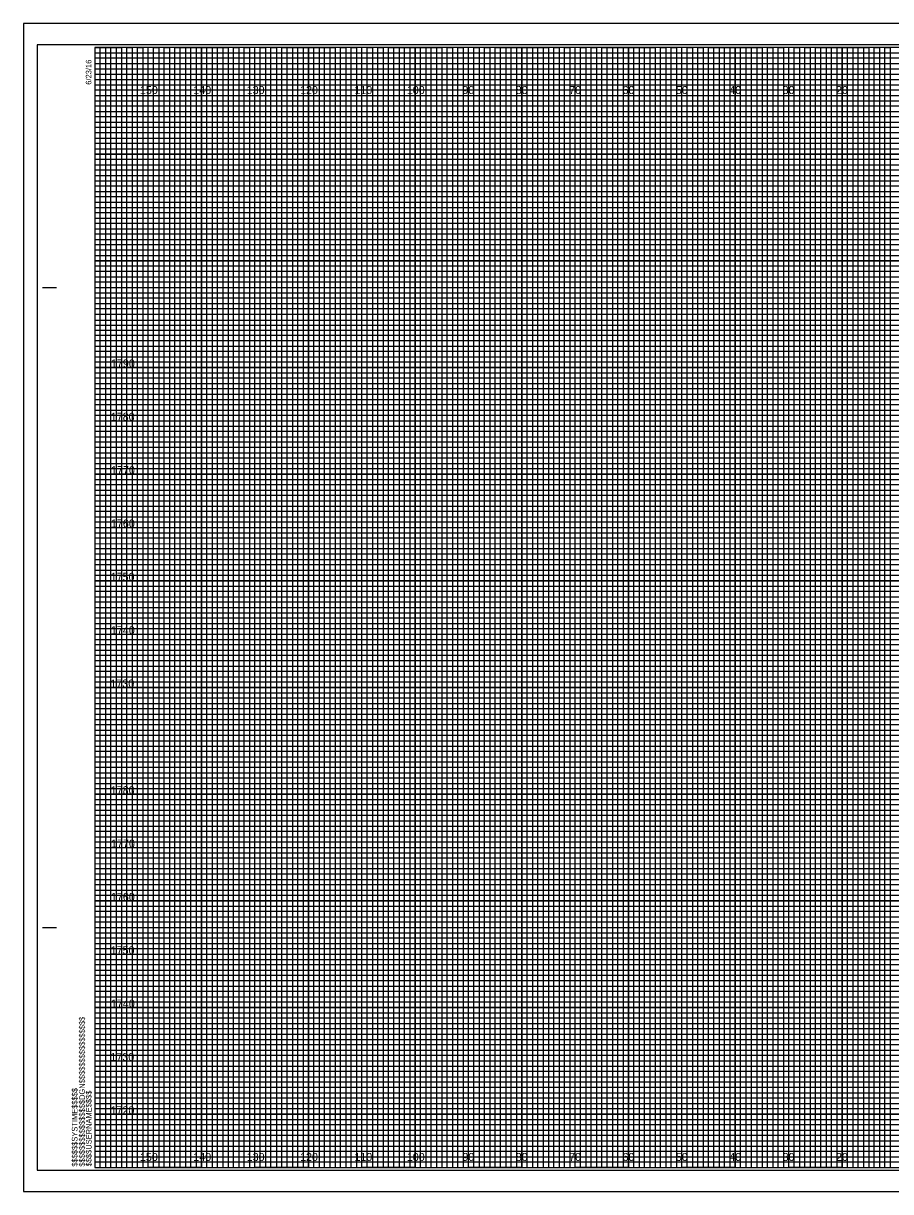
# Model space of a CAD drawing. Extents: x 570 to 907, y -9 to 870.
# Drawn here: x 570.4 to 732.9, y 430.6 to 649.6 of the extents above; entities that cross this region are included whole.
import ezdxf

# ---------------------------------------------------------------- set-up
doc = ezdxf.new("R2010")
doc.units = 0
for name, color, linetype in [('Prop XS Earthwork Shape', 7, 'Continuous'), ('Raster_Level_0', 7, 'Continuous'), ('Scratch_Level_3', 7, 'Continuous'), ('Sheet Cross Section CELL', 7, 'Continuous'), ('Sheet Cross Section Grid Middle CELL', 7, 'Continuous'), ('Sheet Cross Section Grid Minor 1 CELL', 7, 'Continuous'), ('Sheet Cross Section Grid Minor 2 CELL', 7, 'Continuous'), ('Sheet Cutting Line CELL', 7, 'Continuous'), ('Sheet DOT Grid CELL', 7, 'Continuous'), ('Sheet Plot Border Inside CELL', 7, 'Continuous'), ('Sheet Plot Border Outside CELL', 7, 'Continuous')]:
    doc.layers.add(name, color=color, linetype=linetype)

msp = doc.modelspace()

# ---------------------------------------------------------------- linework, layer by layer
at = {"layer": 'Prop XS Earthwork Shape'}
for p, q in [((593.77, 645.14), (583.77, 645.14)), ((593.77, 435.14), (593.77, 645.14)), ((613.77, 645.14), (603.77, 645.14)), ((603.77, 645.14), (603.77, 435.14)), ((613.77, 435.14), (613.77, 645.14)), ((633.77, 645.14), (623.77, 645.14)), ((623.77, 645.14), (623.77, 435.14)), ((633.77, 435.14), (633.77, 645.14)), ((653.77, 645.14), (643.77, 645.14)), ((643.77, 645.14), (643.77, 435.14)), ((653.77, 435.14), (653.77, 645.14)), ((673.77, 645.14), (663.77, 645.14)), ((663.77, 645.14), (663.77, 435.14)), ((673.77, 435.14), (673.77, 645.14)), ((693.77, 645.14), (683.77, 645.14)), ((683.77, 645.14), (683.77, 435.14)), ((693.77, 435.14), (693.77, 645.14)), ((713.77, 645.14), (703.77, 645.14)), ((703.77, 645.14), (703.77, 435.14)), ((713.77, 435.14), (713.77, 645.14)), ((733.77, 645.14), (723.77, 645.14)), ((723.77, 645.14), (723.77, 435.14)), ((603.77, 435.14), (593.77, 435.14)), ((623.77, 435.14), (613.77, 435.14)), ((643.77, 435.14), (633.77, 435.14)), ((663.77, 435.14), (653.77, 435.14)), ((683.77, 435.14), (673.77, 435.14)), ((703.77, 435.14), (693.77, 435.14)), ((723.77, 435.14), (713.77, 435.14))]:
    msp.add_line(p, q, dxfattribs=at)
for points in [[(583.77, 635.14), (903.77, 635.14), (903.77, 625.14), (583.77, 625.14)], [(583.77, 615.14), (903.77, 615.14), (903.77, 605.14), (583.77, 605.14)], [(583.77, 595.14), (903.77, 595.14), (903.77, 585.14), (583.77, 585.14)], [(583.77, 575.14), (903.77, 575.14), (903.77, 565.14), (583.77, 565.14)], [(583.77, 555.14), (903.77, 555.14), (903.77, 545.14), (583.77, 545.14)], [(583.77, 535.14), (903.77, 535.14), (903.77, 525.14), (583.77, 525.14)], [(583.77, 515.14), (903.77, 515.14), (903.77, 505.14), (583.77, 505.14)], [(583.77, 495.14), (903.77, 495.14), (903.77, 485.14), (583.77, 485.14)], [(583.77, 475.14), (903.77, 475.14), (903.77, 465.14), (583.77, 465.14)], [(583.77, 455.14), (903.77, 455.14), (903.77, 445.14), (583.77, 445.14)]]:
    msp.add_lwpolyline(points, dxfattribs=at)
at = {"layer": 'Sheet Cross Section CELL'}
for p, q in [((573.97, 600.14), (576.47, 600.14)), ((574.07, 600.14), (576.57, 600.14)), ((573.97, 480.14), (576.47, 480.14)), ((574.07, 480.14), (576.57, 480.14)), ((583.77, 435.14), (583.77, 435.14)), ((583.77, 435.14), (583.77, 435.14)), ((583.77, 435.14), (583.77, 435.14)), ((583.77, 435.14), (583.77, 435.14)), ((583.77, 435.14), (583.77, 435.14)), ((583.77, 435.14), (583.77, 435.14)), ((583.77, 435.14), (583.77, 435.14))]:
    msp.add_line(p, q, dxfattribs=at)
msp.add_lwpolyline([(903.77, 645.14), (583.77, 645.14), (583.77, 435.14), (903.77, 435.14)], close=True, dxfattribs=at)
at = {"layer": 'Sheet Cross Section Grid Middle CELL'}
for points in [[(583.77, 645.14), (588.77, 645.14), (588.77, 435.14), (598.77, 435.14), (598.77, 645.14), (608.77, 645.14), (608.77, 435.14), (618.77, 435.14), (618.77, 645.14), (628.77, 645.14), (628.77, 435.14), (638.77, 435.14), (638.77, 645.14), (648.77, 645.14), (648.77, 435.14), (658.77, 435.14), (658.77, 645.14), (668.77, 645.14), (668.77, 435.14), (678.77, 435.14), (678.77, 645.14), (688.77, 645.14), (688.77, 435.14), (698.77, 435.14), (698.77, 645.14), (708.77, 645.14), (708.77, 435.14), (718.77, 435.14), (718.77, 645.14), (728.77, 645.14), (728.77, 435.14), (738.77, 435.14)], [(583.77, 640.14), (858.77, 640.14)], [(583.77, 620.14), (903.77, 620.14), (903.77, 630.14), (583.77, 630.14)], [(583.77, 600.14), (903.77, 600.14), (903.77, 610.14), (583.77, 610.14)], [(583.77, 580.14), (903.77, 580.14), (903.77, 590.14), (583.77, 590.14)], [(583.77, 560.14), (903.77, 560.14), (903.77, 570.14), (583.77, 570.14)], [(583.77, 540.14), (903.77, 540.14), (903.77, 550.14), (583.77, 550.14)], [(583.77, 520.14), (903.77, 520.14), (903.77, 530.14), (583.77, 530.14)], [(583.77, 500.14), (903.77, 500.14), (903.77, 510.14), (583.77, 510.14)], [(583.77, 480.14), (903.77, 480.14), (903.77, 490.14), (583.77, 490.14)], [(583.77, 460.14), (903.77, 460.14), (903.77, 470.14), (583.77, 470.14)], [(583.77, 440.14), (903.77, 440.14), (903.77, 450.14), (583.77, 450.14)]]:
    msp.add_lwpolyline(points, dxfattribs=at)
at = {"layer": 'Sheet Cross Section Grid Minor 1 CELL'}
for p, q in [((583.77, 644.14), (843.77, 644.14)), ((843.77, 643.12), (583.77, 643.12)), ((583.77, 643.12), (583.77, 642.14)), ((583.77, 642.14), (843.77, 642.14)), ((843.77, 641.03), (583.77, 641.03)), ((583.77, 641.03), (583.77, 639.14)), ((583.77, 639.14), (903.77, 639.14))]:
    msp.add_line(p, q, dxfattribs=at)
for points in [[(583.77, 638.14), (853.77, 638.14), (903.77, 638.14), (903.77, 637.14), (583.77, 637.14)], [(583.77, 636.14), (903.77, 636.14), (903.77, 634.14), (583.77, 634.14)], [(583.77, 633.14), (903.77, 633.14), (903.77, 632.14), (583.77, 632.12)], [(583.77, 631.14), (903.77, 631.14), (903.77, 629.14), (583.77, 629.14)], [(583.77, 628.14), (903.77, 628.14), (903.77, 627.14), (583.77, 627.14)], [(583.77, 626.14), (903.77, 626.14), (903.77, 624.14), (583.77, 624.14)], [(583.77, 623.14), (903.77, 623.14), (903.77, 622.14), (583.77, 622.14)], [(583.77, 621.14), (903.77, 621.14), (903.77, 619.14), (583.77, 619.14)], [(583.77, 618.14), (903.77, 618.14), (903.77, 617.14), (583.77, 617.14)], [(583.77, 616.14), (903.77, 616.14), (903.77, 614.14), (583.77, 614.14)], [(583.77, 613.14), (903.77, 613.14), (903.77, 612.14), (583.77, 612.14)], [(583.77, 611.14), (903.77, 611.14), (903.77, 609.09), (903.77, 608.14), (903.77, 607.14), (583.77, 607.14)], [(583.77, 609.14), (903.77, 609.14), (903.77, 608.14), (583.77, 608.14)], [(583.77, 606.14), (903.77, 606.14), (903.77, 604.14), (583.77, 604.17)], [(583.77, 604.17), (903.77, 604.14), (903.77, 603.14), (583.77, 603.14)], [(583.77, 602.14), (903.77, 602.14), (903.77, 601.14), (583.77, 601.14)], [(583.77, 599.14), (903.77, 599.14), (903.77, 598.14), (583.77, 598.14)], [(583.77, 597.14), (903.77, 597.14), (903.77, 596.14), (583.77, 596.14)], [(583.7, 594.03), (903.77, 594.03), (903.77, 593.02), (583.7, 593.02)], [(583.77, 592.14), (903.77, 592.14), (903.77, 591.14), (583.77, 591.14)], [(583.77, 589.14), (903.77, 589.14), (903.77, 588.14), (583.77, 588.14)], [(583.77, 587.14), (903.77, 587.14), (903.77, 586.14), (583.77, 586.14)], [(583.77, 584.14), (903.77, 584.14), (903.77, 583.14), (583.77, 583.14)], [(583.77, 582.14), (903.77, 582.14), (903.77, 581.14), (583.77, 581.14)], [(583.77, 579.14), (903.77, 579.14), (903.77, 578.14), (583.77, 578.14)], [(583.77, 577.14), (903.77, 577.14), (903.77, 576.14), (583.77, 576.14)], [(583.77, 574.14), (903.77, 574.14), (903.76, 573.12), (583.77, 573.14)], [(583.77, 572.14), (903.77, 572.14), (903.77, 571.14), (583.77, 571.14)], [(583.77, 569.14), (903.77, 569.14), (903.77, 568.14), (583.77, 568.14)], [(583.77, 567.14), (903.77, 567.14), (903.77, 566.14), (583.77, 566.14)], [(583.77, 564.14), (903.77, 564.14), (903.77, 563.14), (583.77, 563.14)], [(583.77, 562.14), (903.77, 562.14), (903.77, 561.14), (583.77, 561.14)], [(583.77, 559.14), (903.77, 559.14), (903.77, 558.14), (583.77, 558.14)], [(583.77, 557.14), (903.77, 557.14), (903.77, 556.14), (583.77, 556.14)], [(583.77, 554.14), (903.77, 554.14), (903.77, 553.14), (583.77, 553.14)], [(583.77, 552.13), (903.84, 552.05), (903.77, 551.14), (583.77, 551.14)], [(583.77, 549.14), (903.77, 549.14), (903.77, 548.14), (583.77, 548.14)], [(583.77, 547.14), (903.77, 547.14), (903.77, 546.14), (583.77, 546.14)], [(583.77, 544.14), (903.77, 544.14), (903.77, 543.14), (583.77, 543.14)], [(583.77, 542.14), (903.77, 542.14), (903.77, 541.14), (583.77, 541.14)], [(583.77, 539.14), (903.77, 539.14), (903.77, 538.14), (583.77, 538.14)], [(583.77, 537.14), (903.77, 537.14), (903.77, 536.14), (583.77, 536.14)], [(583.77, 534.14), (903.77, 534.14), (903.77, 533.14), (583.77, 533.14)], [(583.77, 532.14), (903.77, 532.14), (903.77, 531.14), (583.77, 531.14)], [(583.77, 529.14), (903.77, 529.14), (903.77, 528.14), (583.77, 528.14)], [(583.77, 527.14), (903.77, 527.14), (903.77, 526.14), (583.77, 526.14)], [(583.77, 524.14), (903.77, 524.14), (903.77, 523.14), (583.77, 523.14)], [(583.77, 522.14), (903.77, 522.14), (903.77, 521.14), (583.77, 521.14)], [(583.77, 519.14), (903.77, 519.14), (903.77, 518.14), (583.77, 518.14)], [(583.77, 517.14), (903.77, 517.14), (903.77, 516.14), (583.77, 516.14)], [(583.77, 514.14), (903.77, 514.14), (903.76, 513.12), (583.77, 513.14)], [(583.77, 512.14), (903.77, 512.14), (903.77, 511.14), (583.77, 511.14)], [(583.77, 509.14), (903.77, 509.14), (903.77, 508.14), (583.77, 508.14)], [(583.77, 507.14), (903.77, 507.14), (903.77, 506.14), (583.77, 506.14)], [(583.77, 504.14), (903.77, 504.14), (903.77, 503.14), (583.77, 503.14)], [(583.77, 502.14), (903.77, 502.14), (903.77, 501.14), (583.77, 501.14)], [(583.77, 499.14), (903.77, 499.14), (903.77, 498.14), (583.77, 498.14)], [(583.77, 497.14), (903.77, 497.14), (903.77, 496.14), (583.77, 496.14)], [(583.77, 494.14), (903.77, 494.14), (903.77, 493.14), (583.77, 493.14)], [(583.77, 492.13), (903.84, 492.05), (903.77, 491.14), (583.77, 491.14)], [(583.77, 489.14), (903.77, 489.14), (903.77, 488.14), (583.77, 488.14)], [(583.77, 487.14), (903.77, 487.14), (903.77, 486.14), (583.77, 486.14)], [(583.77, 484.14), (903.77, 484.14), (903.77, 483.14), (583.77, 483.14)], [(583.77, 482.14), (903.77, 482.14), (903.77, 481.14), (583.77, 481.14)], [(583.77, 479.14), (903.77, 479.14), (903.77, 478.14), (583.77, 478.14)], [(583.77, 477.14), (903.77, 477.14), (903.77, 476.14), (583.77, 476.14)], [(583.77, 474.14), (903.77, 474.14), (903.77, 473.14), (583.77, 473.14)], [(583.77, 472.14), (903.77, 472.14), (903.77, 471.14), (583.77, 471.14)], [(583.77, 469.14), (903.77, 469.14), (903.77, 468.14), (583.77, 468.14)], [(583.77, 467.14), (903.77, 467.14), (903.77, 466.14), (583.77, 466.14)], [(583.77, 464.14), (903.77, 464.14), (903.77, 463.14), (583.77, 463.14)], [(583.77, 462.14), (903.77, 462.14), (903.77, 461.14), (583.77, 461.14)], [(583.77, 459.14), (903.77, 459.14), (903.77, 458.14), (583.77, 458.14)], [(583.77, 457.14), (903.77, 457.14), (903.77, 456.14), (583.77, 456.14)], [(583.77, 454.14), (903.77, 454.14), (903.77, 453.14), (583.77, 453.14)], [(583.77, 452.14), (903.77, 452.14), (903.77, 451.14), (583.77, 451.14)], [(583.77, 449.14), (903.77, 449.14), (903.77, 448.14), (583.77, 448.14)], [(583.77, 447.14), (903.77, 447.14), (903.77, 446.14), (583.77, 446.14)], [(583.77, 444.14), (903.77, 444.14), (903.77, 443.14), (583.77, 443.14)], [(583.77, 442.14), (903.77, 442.14), (903.77, 441.14), (583.77, 441.14)], [(583.77, 439.14), (903.77, 439.14), (903.77, 438.14), (583.77, 438.14)], [(583.77, 437.14), (903.77, 437.14), (903.77, 436.14), (583.77, 436.14)]]:
    msp.add_lwpolyline(points, dxfattribs=at)
at = {"layer": 'Sheet Cross Section Grid Minor 2 CELL'}
for points in [[(583.77, 435.14), (584.77, 435.14), (584.77, 645.14), (585.77, 645.14), (585.77, 435.14)], [(585.77, 435.14), (586.77, 435.14), (586.77, 645.14), (587.77, 645.14), (587.77, 435.14)], [(588.77, 435.14), (589.77, 435.14), (589.77, 645.14), (590.77, 645.14), (590.77, 435.14)], [(590.77, 435.14), (591.77, 435.14), (591.77, 645.14), (592.77, 645.14), (592.77, 435.14)], [(593.77, 435.14), (594.77, 435.14), (594.77, 645.14), (595.77, 645.14), (595.77, 435.14)], [(595.77, 435.14), (596.77, 435.14), (596.77, 645.14), (597.77, 645.14), (597.77, 435.14)], [(598.77, 435.14), (599.77, 435.14), (599.77, 645.14), (600.77, 645.14), (600.77, 435.14)], [(600.77, 435.14), (601.77, 435.14), (601.77, 645.14), (602.77, 645.14), (602.77, 435.14)], [(603.77, 435.14), (604.77, 435.14), (604.77, 645.14), (605.77, 645.14), (605.77, 435.14)], [(605.77, 435.14), (606.77, 435.14), (606.77, 645.14), (607.77, 645.14), (607.77, 435.14)], [(608.77, 435.14), (609.77, 435.14), (609.77, 645.14), (610.77, 645.14), (610.77, 435.14)], [(610.77, 435.14), (611.77, 435.14), (611.77, 645.14), (612.77, 645.14), (612.77, 435.14)], [(613.77, 435.14), (614.77, 435.14), (614.77, 645.14), (615.77, 645.14), (615.77, 435.14)], [(615.77, 435.14), (616.77, 435.14), (616.77, 645.14), (617.77, 645.14), (617.77, 435.14)], [(618.77, 435.14), (619.77, 435.14), (619.77, 645.14), (620.77, 645.14), (620.77, 435.14)], [(620.77, 435.14), (621.77, 435.14), (621.77, 645.14), (622.77, 645.14), (622.77, 435.14)], [(623.77, 435.14), (624.77, 435.14), (624.77, 645.14), (625.77, 645.14), (625.77, 435.14)], [(625.77, 435.14), (626.77, 435.14), (626.77, 645.14), (627.77, 645.14), (627.77, 435.14)], [(628.77, 435.14), (629.77, 435.14), (629.77, 645.14), (630.77, 645.14), (630.77, 435.14)], [(630.77, 435.14), (631.77, 435.14), (631.77, 645.14), (632.77, 645.14), (632.77, 435.14)], [(633.77, 435.14), (634.77, 435.14), (634.77, 645.14), (635.77, 645.14), (635.77, 435.14)], [(635.77, 435.14), (636.77, 435.14), (636.77, 645.14), (637.77, 645.14), (637.77, 435.14)], [(638.77, 435.14), (639.77, 435.14), (639.77, 645.14), (640.77, 645.14), (640.77, 435.14)], [(640.77, 435.14), (641.77, 435.14), (641.77, 645.14), (642.77, 645.14), (642.77, 435.14)], [(643.77, 435.14), (644.77, 435.14), (644.77, 645.14), (645.77, 645.14), (645.77, 435.14)], [(645.77, 435.14), (646.77, 435.14), (646.77, 645.14), (647.77, 645.14), (647.77, 435.14)], [(648.77, 435.14), (649.77, 435.14), (649.77, 645.14), (650.77, 645.14), (650.77, 435.14)], [(650.77, 435.14), (651.77, 435.14), (651.77, 645.14), (652.77, 645.14), (652.77, 435.14)], [(653.77, 435.14), (654.77, 435.14), (654.77, 645.14), (655.77, 645.14), (655.77, 435.14)], [(655.77, 435.14), (656.77, 435.14), (656.77, 645.14), (657.77, 645.14), (657.77, 435.14)], [(658.77, 435.14), (659.77, 435.14), (659.77, 645.14), (660.77, 645.14), (660.77, 435.14)], [(660.77, 435.14), (661.77, 435.14), (661.77, 645.14), (662.77, 645.14), (662.77, 435.14)], [(663.77, 435.14), (664.77, 435.14), (664.77, 645.14), (665.77, 645.14), (665.77, 435.14)], [(665.77, 435.14), (666.77, 435.14), (666.77, 645.14), (667.77, 645.14), (667.77, 435.14)], [(668.77, 435.14), (669.77, 435.14), (669.77, 645.14), (670.77, 645.14), (670.77, 435.14)], [(670.77, 435.14), (671.77, 435.14), (671.77, 645.14), (672.77, 645.14), (672.77, 435.14)], [(673.77, 435.14), (674.77, 435.14), (674.77, 645.14), (675.77, 645.14), (675.77, 435.14)], [(675.77, 435.14), (676.77, 435.14), (676.77, 645.14), (677.77, 645.14), (677.77, 435.14)], [(678.77, 435.14), (679.77, 435.14), (679.77, 645.14), (680.77, 645.14), (680.77, 435.14)], [(680.77, 435.14), (681.77, 435.14), (681.77, 645.14), (682.77, 645.14), (682.77, 435.14)], [(683.77, 435.14), (684.77, 435.14), (684.77, 645.14), (685.77, 645.14), (685.77, 435.14)], [(685.77, 435.14), (686.77, 435.14), (686.77, 645.14), (687.77, 645.14), (687.77, 435.14)], [(688.77, 435.14), (689.77, 435.14), (689.77, 645.14), (690.77, 645.14), (690.77, 435.14)], [(690.77, 435.14), (691.77, 435.14), (691.77, 645.14), (692.77, 645.14), (692.77, 435.14)], [(693.77, 435.14), (694.77, 435.14), (694.77, 645.14), (695.77, 645.14), (695.77, 435.14)], [(695.77, 435.14), (696.77, 435.14), (696.77, 645.14), (697.77, 645.14), (697.77, 435.14)], [(698.77, 435.14), (699.77, 435.14), (699.77, 645.14), (700.77, 645.14), (700.77, 435.14)], [(700.77, 435.14), (701.77, 435.14), (701.77, 645.14), (702.77, 645.14), (702.77, 435.14)], [(703.77, 435.14), (704.77, 435.14), (704.77, 645.14), (705.77, 645.14), (705.77, 435.14)], [(705.77, 435.14), (706.77, 435.14), (706.77, 645.14), (707.77, 645.14), (707.77, 435.14)], [(708.77, 435.14), (709.77, 435.14), (709.77, 645.14), (710.77, 645.14), (710.77, 435.14)], [(710.77, 435.14), (711.77, 435.14), (711.77, 645.14), (712.77, 645.14), (712.77, 435.14)], [(713.77, 435.14), (714.77, 435.14), (714.77, 645.14), (715.77, 645.14), (715.77, 435.14)], [(715.77, 435.14), (716.77, 435.14), (716.77, 645.14), (717.77, 645.14), (717.77, 435.14)], [(718.77, 435.14), (719.77, 435.14), (719.77, 645.14), (720.77, 645.14), (720.77, 435.14)], [(720.77, 435.14), (721.77, 435.14), (721.77, 645.14), (722.77, 645.14), (722.77, 435.14)], [(723.77, 435.14), (724.77, 435.14), (724.77, 645.14), (725.77, 645.14), (725.77, 435.14)], [(725.77, 435.14), (726.77, 435.14), (726.77, 645.14), (727.77, 645.14), (727.77, 435.14)], [(728.77, 435.14), (729.77, 435.14), (729.77, 645.14), (730.77, 645.14), (730.77, 435.14)], [(730.77, 435.14), (731.77, 435.14), (731.77, 645.14), (732.77, 645.14), (732.77, 435.14)]]:
    msp.add_lwpolyline(points, dxfattribs=at)
at = {"layer": 'Sheet Cutting Line CELL'}
for p, q in [((907.07, 649.64), (570.37, 649.64)), ((570.37, 649.64), (570.37, 430.64)), ((570.37, 430.64), (907.07, 430.64))]:
    msp.add_line(p, q, dxfattribs=at)
at = {"layer": 'Sheet DOT Grid CELL'}
for p, q in [((593.77, 435.14), (593.77, 645.14)), ((603.77, 435.14), (603.77, 645.14)), ((613.77, 435.14), (613.77, 645.14)), ((623.77, 435.14), (623.77, 645.14)), ((633.77, 435.14), (633.77, 645.14)), ((643.77, 435.14), (643.77, 645.14)), ((653.77, 435.14), (653.77, 645.14)), ((663.77, 435.14), (663.77, 645.14)), ((673.77, 435.14), (673.77, 645.14)), ((683.77, 435.14), (683.77, 645.14)), ((693.77, 435.14), (693.77, 645.14)), ((703.77, 435.14), (703.77, 645.14)), ((713.77, 435.14), (713.77, 645.14)), ((723.77, 435.14), (723.77, 645.14)), ((583.77, 635.14), (903.77, 635.14)), ((583.77, 625.14), (903.77, 625.14)), ((583.77, 615.14), (903.77, 615.14)), ((583.77, 605.14), (903.77, 605.14)), ((583.77, 595.14), (903.77, 595.14)), ((583.77, 585.14), (903.77, 585.14)), ((583.77, 575.14), (903.77, 575.14)), ((583.77, 565.14), (903.77, 565.14)), ((583.77, 555.14), (903.77, 555.14)), ((583.77, 545.14), (903.77, 545.14)), ((583.77, 535.14), (903.77, 535.14)), ((583.77, 525.14), (903.77, 525.14)), ((583.77, 515.14), (903.77, 515.14)), ((583.77, 505.14), (903.77, 505.14)), ((583.77, 495.14), (903.77, 495.14)), ((583.77, 485.14), (903.77, 485.14)), ((583.77, 475.14), (903.77, 475.14)), ((583.77, 465.14), (903.77, 465.14)), ((583.77, 455.14), (903.77, 455.14)), ((583.77, 445.14), (903.77, 445.14))]:
    msp.add_line(p, q, dxfattribs=at)
at = {"layer": 'Sheet Plot Border Inside CELL'}
msp.add_lwpolyline([(572.97, 434.64), (906.17, 434.64), (906.17, 645.64), (572.97, 645.64)], close=True, dxfattribs=at)
at = {"layer": 'Sheet Plot Border Outside CELL'}
msp.add_lwpolyline([(570.37, 430.64), (907.07, 430.64), (907.07, 649.64), (570.37, 649.64)], close=True, dxfattribs=at)

# ---------------------------------------------------------------- texts
at = {"layer": 'Raster_Level_0'}
for s, p in [('150', (592.22, 636.39)), ('140', (602.22, 636.39)), ('130', (612.22, 636.39)), ('120', (622.22, 636.39)), ('110', (632.4, 636.39)), ('100', (642.22, 636.39)), ('90', (652.63, 636.39)), ('80', (662.63, 636.39)), ('70', (672.63, 636.39)), ('60', (682.63, 636.39)), ('50', (692.63, 636.39)), ('40', (702.63, 636.39)), ('30', (712.63, 636.39)), ('20', (722.63, 636.39)), ('150', (592.22, 436.39)), ('140', (602.22, 436.39)), ('130', (612.22, 436.39)), ('120', (622.22, 436.39)), ('110', (632.4, 436.39)), ('100', (642.22, 436.39)), ('90', (652.63, 436.39)), ('80', (662.63, 436.39)), ('70', (672.63, 436.39)), ('60', (682.63, 436.39)), ('50', (692.63, 436.39)), ('40', (702.63, 436.39)), ('30', (712.63, 436.39)), ('20', (722.63, 436.39))]:
    msp.add_text(s, height=1.5, dxfattribs=at).set_placement(p)
at = {"layer": 'Scratch_Level_3'}
for s, p in [('1790', (586.78, 585.14)), ('1780', (586.75, 575.14)), ('1770', (586.81, 565.14)), ('1760', (586.78, 555.14)), ('1750', (586.73, 545.14)), ('1740', (586.78, 535.14)), ('1730', (586.69, 525.14)), ('1780', (586.75, 505.14)), ('1770', (586.81, 495.14)), ('1760', (586.78, 485.14)), ('1750', (586.73, 475.14)), ('1740', (586.78, 465.14)), ('1730', (586.69, 455.14)), ('1720', (586.71, 445.14))]:
    msp.add_text(s, height=1.5, dxfattribs=at).set_placement(p)
at = {"layer": 'Sheet Cross Section CELL'}
for s, p in [('6/23/16', (583.12, 638.14)), ('$$$$$$$$$$$$$$$$DGN$$$$$$$$$$$$$$$$', (581.89, 435.32)), ('$$$$$$SYSTIME$$$$$', (580.51, 435.32)), ('$$$$USERNAME$$$$', (583.15, 435.37))]:
    msp.add_text(s, height=1.05, rotation=90, dxfattribs=at).set_placement(p)

doc.saveas('drawing.dxf')
